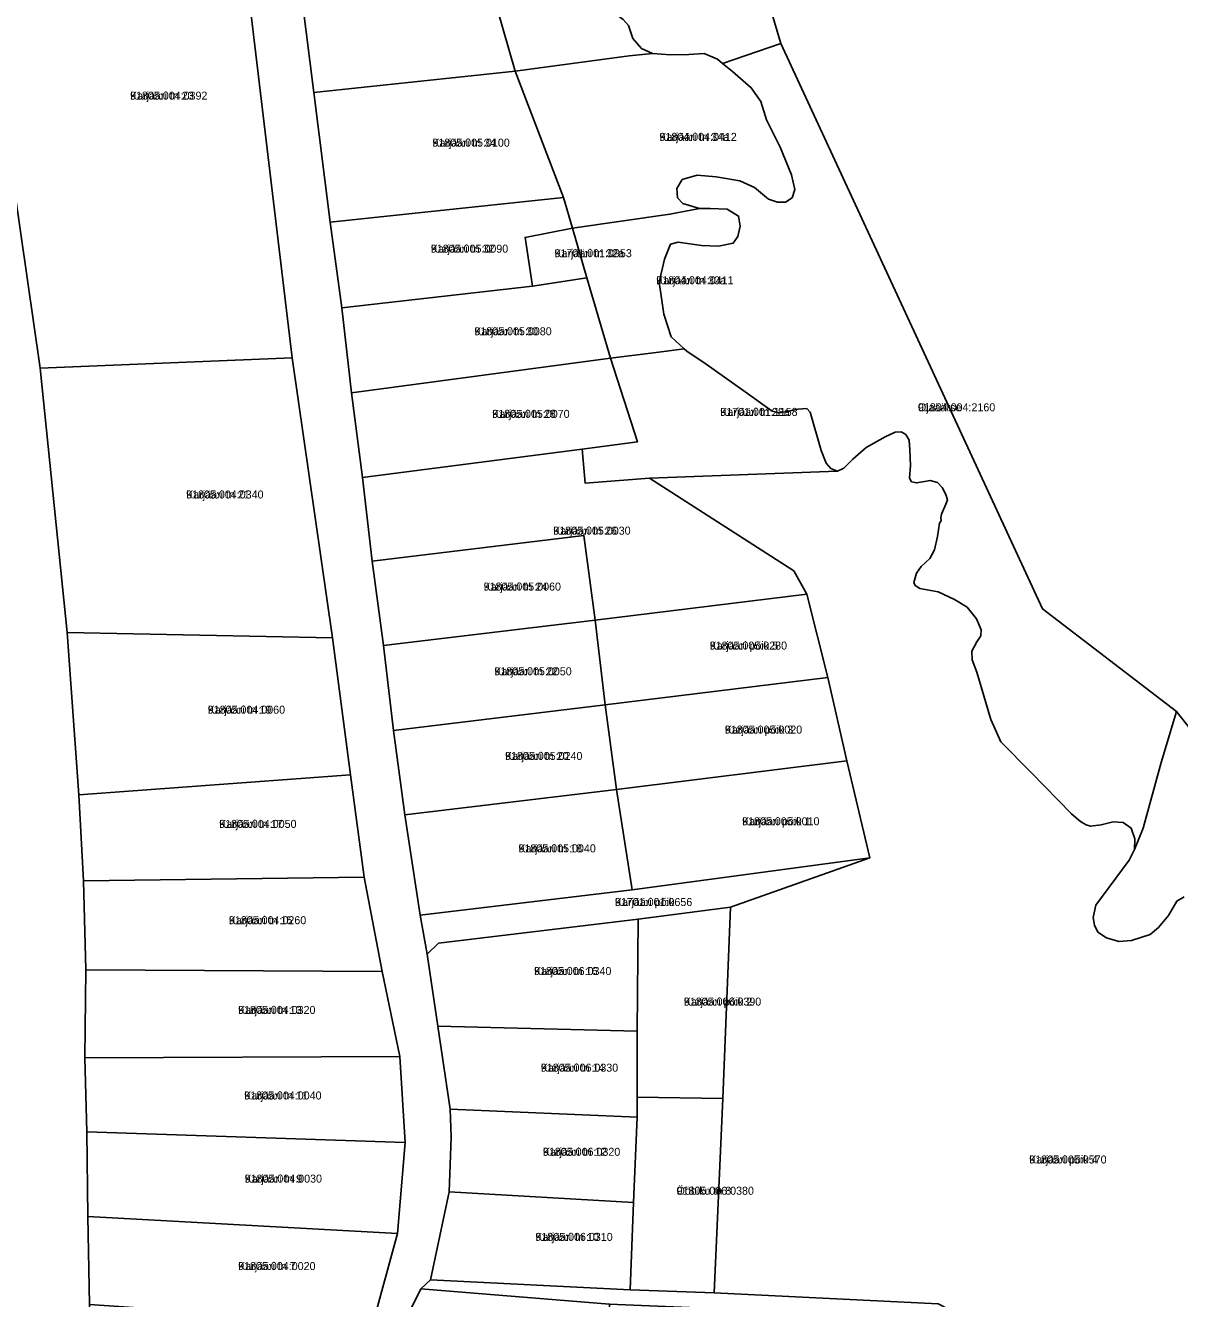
# Model space of a CAD drawing. Extents: x 655954 to 711923, y 6395079 to 6429745.
# Drawn here: x 680691.2 to 680907.6, y 6412288.3 to 6412527 of the extents above; entities that cross this region are included whole.
import ezdxf

# ---------------------------------------------------------------- set-up
doc = ezdxf.new("R2010")
doc.units = 0
for name, color, linetype in [('L_AADRESS', 7, 'Continuous'), ('PIIR', 7, 'Continuous'), ('TUNNUS', 7, 'Continuous')]:
    doc.layers.add(name, color=color, linetype=linetype)

msp = doc.modelspace()

# ---------------------------------------------------------------- linework, layer by layer
at = {"layer": 'PIIR'}
for points in [[(681631.25, 6412784.39), (681524.04, 6412713.27), (681400.11, 6412655.35), (681158.01, 6412526.04), (681124.39, 6412504.87), (681051.56, 6412457.34), (681017.07, 6412435.31), (681004.5, 6412429.19), (680916.58, 6412386.27), (680907.04, 6412398.35), (680881.9, 6412417.62), (680832.81, 6412523.6), (680811.9, 6412594.2), (680849.16, 6412621.46), (680903.12, 6412670.17), (681120.91, 6412675.42), (681109.41, 6412705.01), (680986.04, 6412708.3), (680879.12, 6412719.8), (680806.44, 6412709.75), (680770.1, 6412691.18), (680731.48, 6412687.34), (680659.4, 6412646.08)], [(680811.9, 6412594.2), (680832.81, 6412523.6), (680821.91, 6412519.87), (680820.95, 6412520.65), (680818.44, 6412521.74), (680815.59, 6412521.55), (680812.14, 6412521.48), (680808.77, 6412521.73), (680806.72, 6412522.65), (680805.08, 6412524.57), (680804.29, 6412526.99), (680803.3, 6412528.1)], [(680680.44, 6412556.2), (680693.94, 6412462.74), (680699, 6412413.21), (680701.22, 6412382.72), (680702.09, 6412366.63), (680702.52, 6412349.92), (680702.33, 6412333.42), (680702.73, 6412319.59), (680702.93, 6412303.72), (680703.22, 6412287.2), (680703.43, 6412273.22), (680703.41, 6412251.32), (680702.8, 6412190.26), (680703.14, 6412141.77), (680698.64, 6412123.91), (680691.94, 6412100.04), (680672.88, 6412104.96)], [(680756.31, 6412283.58), (680760.94, 6412300.49), (680762.39, 6412317.56), (680761.38, 6412333.7), (680758.07, 6412349.64), (680754.74, 6412367.34), (680752.17, 6412386.48), (680748.75, 6412412.17), (680741.2, 6412464.7), (680732.66, 6412536.32)], [(680742.3, 6412538.26), (680745.27, 6412514.43), (680748.34, 6412490.12), (680750.51, 6412474.03), (680752.34, 6412458.13), (680754.39, 6412442.26), (680756.2, 6412426.58), (680758.31, 6412410.72), (680760.22, 6412394.83), (680762.32, 6412378.97), (680765.23, 6412360.19), (680766.53, 6412352.85), (680768.52, 6412339.36), (680770.82, 6412323.82), (680771.02, 6412318.58), (680770.65, 6412308.3), (680767.12, 6412291.79), (680765.34, 6412290.1), (680752.9, 6412265.02)], [(680862.31, 6412287.31), (680820.36, 6412289.35), (680821.96, 6412325.79), (680823.43, 6412361.7), (680849.55, 6412370.94), (680845.2, 6412389.13), (680841.62, 6412404.73), (680837.72, 6412420.36), (680835.28, 6412424.73), (680808.22, 6412442.15), (680843.48, 6412443.45), (680844.64, 6412444), (680846.33, 6412445.67), (680848.83, 6412447.85), (680852.42, 6412449.87), (680854.27, 6412450.76), (680855.38, 6412450.81), (680856.28, 6412450.29), (680856.87, 6412449.23), (680857.02, 6412447.46), (680857.18, 6412444.47), (680856.96, 6412442.14), (680857.35, 6412441.46), (680858.25, 6412441.22), (680859.77, 6412441.48), (680860.85, 6412441.69), (680862.19, 6412441.3), (680863.09, 6412440.39), (680863.78, 6412439.05), (680864.07, 6412438.04), (680863.75, 6412437.23), (680862.97, 6412435.39), (680862.85, 6412434.68), (680862.87, 6412434.14), (680862.6, 6412433.71), (680862.23, 6412431.17), (680861.64, 6412428.66), (680860.8, 6412427.05), (680859.18, 6412425.57), (680858.25, 6412424.31), (680857.75, 6412422.53), (680858.02, 6412421.98), (680858.92, 6412421.46), (680862.32, 6412420.79), (680865.43, 6412419.39), (680867.75, 6412417.94), (680869.55, 6412415.72), (680870.4, 6412413.67), (680870.35, 6412412.54), (680869.56, 6412411.45), (680868.66, 6412409.69), (680868.71, 6412408.09), (680869.61, 6412405.76), (680872.21, 6412396.87), (680874.07, 6412392.69), (680879.76, 6412386.94), (680887.36, 6412379.16), (680888.71, 6412378.03), (680889.21, 6412377.62), (680890.06, 6412377.14), (680890.93, 6412376.9), (680892.91, 6412377.1), (680895.18, 6412377.69), (680897.04, 6412377.58), (680898.52, 6412376.49), (680899.19, 6412374.52), (680899.13, 6412372.51), (680898.17, 6412370.5), (680891.93, 6412362.05), (680891.41, 6412359.77), (680891.62, 6412358.34), (680892.25, 6412357.02), (680893.89, 6412355.91), (680896.22, 6412355.28), (680898.6, 6412355.43), (680902.09, 6412356.54), (680903.63, 6412357.87), (680905.53, 6412360.14), (680907.07, 6412362.84), (680908.44, 6412363.63)], [(680908.44, 6412363.63), (680907.07, 6412362.84), (680905.53, 6412360.14), (680903.63, 6412357.87), (680902.09, 6412356.54), (680898.6, 6412355.43), (680896.22, 6412355.28), (680893.89, 6412355.91), (680892.25, 6412357.02), (680891.62, 6412358.34), (680891.41, 6412359.77), (680891.93, 6412362.05), (680898.17, 6412370.5), (680899.13, 6412372.51), (680900.78, 6412376.52), (680904.16, 6412388.82), (680907.04, 6412398.35), (680916.58, 6412386.27)]]:
    msp.add_lwpolyline(points, dxfattribs=at)
for points in [[(680710.88, 6412562.75), (680718, 6412533.21), (680732.66, 6412536.32), (680741.2, 6412464.7), (680693.94, 6412462.74), (680680.44, 6412556.2)], [(680776.14, 6412542.38), (680801.78, 6412545.87), (680805.78, 6412546.39), (680807.55, 6412543.41), (680805.54, 6412539.25), (680801.77, 6412537.65), (680797.26, 6412535.89), (680795.9, 6412535.1), (680795.63, 6412533.76), (680796.33, 6412532.41), (680797.99, 6412531.65), (680799.57, 6412531.08), (680801.29, 6412529.6), (680803.3, 6412528.1), (680804.29, 6412526.99), (680805.08, 6412524.57), (680806.72, 6412522.65), (680808.77, 6412521.73), (680804.4, 6412521.32), (680783.04, 6412518.42)], [(680745.27, 6412514.43), (680742.3, 6412538.26), (680776.14, 6412542.38), (680783.04, 6412518.42)], [(680832.2, 6412493.89), (680830.5, 6412494.41), (680827.92, 6412496.63), (680825.15, 6412497.88), (680820.72, 6412498.59), (680817.12, 6412498.9), (680814.36, 6412498.09), (680813.34, 6412496.44), (680813.49, 6412494.7), (680814.48, 6412493.63), (680817.6, 6412492.68), (680812.05, 6412491.59), (680793.76, 6412488.98), (680792.1, 6412494.76), (680783.04, 6412518.42), (680804.4, 6412521.32), (680808.77, 6412521.73), (680812.14, 6412521.48), (680815.59, 6412521.55), (680818.44, 6412521.74), (680820.95, 6412520.65), (680821.91, 6412519.87), (680823.76, 6412518.34), (680827.28, 6412515.31), (680829.09, 6412512.76), (680830.14, 6412509.33), (680832.69, 6412504.2), (680834.85, 6412498.99), (680835.48, 6412496.27), (680834.97, 6412494.7), (680833.71, 6412493.84)], [(680825.69, 6412458.62), (680818.81, 6412463.48), (680815.2, 6412465.95), (680814.71, 6412466.39), (680812.27, 6412468.61), (680810.89, 6412472.89), (680810.04, 6412478.85), (680811.04, 6412483.2), (680812.16, 6412485.99), (680813.6, 6412486.39), (680817.96, 6412485.73), (680821.15, 6412485.62), (680823.92, 6412486.2), (680824.79, 6412487.43), (680825.21, 6412489.34), (680824.93, 6412491.26), (680822.75, 6412492.55), (680819.58, 6412492.67), (680817.6, 6412492.68), (680814.48, 6412493.63), (680813.49, 6412494.7), (680813.34, 6412496.44), (680814.36, 6412498.09), (680817.12, 6412498.9), (680820.72, 6412498.59), (680825.15, 6412497.88), (680827.92, 6412496.63), (680830.5, 6412494.41), (680832.2, 6412493.89), (680833.71, 6412493.84), (680834.97, 6412494.7), (680835.48, 6412496.27), (680834.85, 6412498.99), (680832.69, 6412504.2), (680830.14, 6412509.33), (680829.09, 6412512.76), (680827.28, 6412515.31), (680823.76, 6412518.34), (680821.91, 6412519.87), (680832.81, 6412523.6), (680881.9, 6412417.62), (680907.04, 6412398.35), (680904.16, 6412388.82), (680900.78, 6412376.52), (680899.13, 6412372.51), (680899.19, 6412374.52), (680898.52, 6412376.49), (680897.04, 6412377.58), (680895.18, 6412377.69), (680892.91, 6412377.1), (680890.93, 6412376.9), (680890.06, 6412377.14), (680889.21, 6412377.62), (680888.71, 6412378.03), (680887.36, 6412379.16), (680879.76, 6412386.94), (680874.07, 6412392.69), (680872.21, 6412396.87), (680869.61, 6412405.76), (680868.71, 6412408.09), (680868.66, 6412409.69), (680869.56, 6412411.45), (680870.35, 6412412.54), (680870.4, 6412413.67), (680869.55, 6412415.72), (680867.75, 6412417.94), (680865.43, 6412419.39), (680862.32, 6412420.79), (680858.92, 6412421.46), (680858.02, 6412421.98), (680857.75, 6412422.53), (680858.25, 6412424.31), (680859.18, 6412425.57), (680860.8, 6412427.05), (680861.64, 6412428.66), (680862.23, 6412431.17), (680862.6, 6412433.71), (680862.87, 6412434.14), (680862.85, 6412434.68), (680862.97, 6412435.39), (680863.75, 6412437.23), (680864.07, 6412438.04), (680863.78, 6412439.05), (680863.09, 6412440.39), (680862.19, 6412441.3), (680860.85, 6412441.69), (680859.77, 6412441.48), (680858.25, 6412441.22), (680857.35, 6412441.46), (680856.96, 6412442.14), (680857.18, 6412444.47), (680857.02, 6412447.46), (680856.87, 6412449.23), (680856.28, 6412450.29), (680855.38, 6412450.81), (680854.27, 6412450.76), (680852.42, 6412449.87), (680848.83, 6412447.85), (680846.33, 6412445.67), (680844.64, 6412444), (680843.48, 6412443.45), (680842.21, 6412443.92), (680841.32, 6412444.91), (680840.41, 6412447.31), (680838.36, 6412454.5), (680837.71, 6412455.17), (680836.08, 6412455.08), (680832.65, 6412454.38), (680831.21, 6412454.66)], [(680745.27, 6412514.43), (680783.04, 6412518.42), (680792.1, 6412494.76), (680748.34, 6412490.12)], [(680748.34, 6412490.12), (680792.1, 6412494.76), (680793.76, 6412488.98), (680784.89, 6412487.26), (680786.28, 6412478.13), (680750.51, 6412474.03)], [(680810.89, 6412472.89), (680812.27, 6412468.61), (680814.71, 6412466.39), (680809.47, 6412465.71), (680800.91, 6412464.6), (680796.45, 6412479.7), (680793.76, 6412488.98), (680812.05, 6412491.59), (680817.6, 6412492.68), (680819.58, 6412492.67), (680822.75, 6412492.55), (680824.93, 6412491.26), (680825.21, 6412489.34), (680824.79, 6412487.43), (680823.92, 6412486.2), (680821.15, 6412485.62), (680817.96, 6412485.73), (680813.6, 6412486.39), (680812.16, 6412485.99), (680811.04, 6412483.2), (680810.04, 6412478.85)], [(680796.45, 6412479.7), (680786.28, 6412478.13), (680784.89, 6412487.26), (680793.76, 6412488.98)], [(680752.34, 6412458.13), (680750.51, 6412474.03), (680786.28, 6412478.13), (680796.45, 6412479.7), (680800.91, 6412464.6)], [(680693.94, 6412462.74), (680741.2, 6412464.7), (680748.75, 6412412.17), (680699, 6412413.21)], [(680800.91, 6412464.6), (680805.96, 6412448.92), (680795.6, 6412447.58), (680754.39, 6412442.26), (680752.34, 6412458.13)], [(680831.21, 6412454.66), (680832.65, 6412454.38), (680836.08, 6412455.08), (680837.71, 6412455.17), (680838.36, 6412454.5), (680840.41, 6412447.31), (680841.32, 6412444.91), (680842.21, 6412443.92), (680843.48, 6412443.45), (680808.22, 6412442.15), (680796.15, 6412441.18), (680795.6, 6412447.58), (680805.96, 6412448.92), (680800.91, 6412464.6), (680809.47, 6412465.71), (680814.71, 6412466.39), (680815.2, 6412465.95), (680818.81, 6412463.48), (680825.69, 6412458.62)], [(680756.2, 6412426.58), (680754.39, 6412442.26), (680795.6, 6412447.58), (680796.15, 6412441.18), (680808.22, 6412442.15), (680835.28, 6412424.73), (680837.72, 6412420.36), (680798.02, 6412415.49), (680795.91, 6412431.35)], [(680756.2, 6412426.58), (680795.91, 6412431.35), (680798.02, 6412415.49), (680758.31, 6412410.72)], [(680799.93, 6412399.6), (680798.02, 6412415.49), (680837.72, 6412420.36), (680841.62, 6412404.73)], [(680758.31, 6412410.72), (680798.02, 6412415.49), (680799.93, 6412399.6), (680760.22, 6412394.83)], [(680748.75, 6412412.17), (680752.17, 6412386.48), (680701.22, 6412382.72), (680699, 6412413.21)], [(680802.04, 6412383.72), (680799.93, 6412399.6), (680841.62, 6412404.73), (680845.2, 6412389.13)], [(680760.22, 6412394.83), (680799.93, 6412399.6), (680802.04, 6412383.72), (680762.32, 6412378.97)], [(680849.55, 6412370.94), (680804.95, 6412364.94), (680802.04, 6412383.72), (680845.2, 6412389.13)], [(680752.17, 6412386.48), (680754.74, 6412367.34), (680702.09, 6412366.63), (680701.22, 6412382.72)], [(680762.32, 6412378.97), (680802.04, 6412383.72), (680804.95, 6412364.94), (680765.23, 6412360.19)], [(680766.53, 6412352.85), (680765.23, 6412360.19), (680804.95, 6412364.94), (680849.55, 6412370.94), (680823.43, 6412361.7), (680806.1, 6412359.44), (680768.67, 6412354.94)], [(680754.74, 6412367.34), (680758.07, 6412349.64), (680702.52, 6412349.92), (680702.09, 6412366.63)], [(680806.1, 6412359.44), (680823.43, 6412361.7), (680821.96, 6412325.79), (680805.89, 6412326.04), (680805.92, 6412338.47)], [(680768.52, 6412339.36), (680766.53, 6412352.85), (680768.67, 6412354.94), (680806.1, 6412359.44), (680805.92, 6412338.47)], [(680758.07, 6412349.64), (680761.38, 6412333.7), (680702.33, 6412333.42), (680702.52, 6412349.92)], [(680770.82, 6412323.82), (680768.52, 6412339.36), (680805.92, 6412338.47), (680805.89, 6412326.04), (680805.88, 6412322.32)], [(680761.38, 6412333.7), (680762.39, 6412317.56), (680702.73, 6412319.59), (680702.33, 6412333.42)], [(680805.89, 6412326.04), (680821.96, 6412325.79), (680820.36, 6412289.35), (680804.61, 6412289.94), (680805.19, 6412306.32), (680805.88, 6412322.32)], [(680771.02, 6412318.58), (680770.82, 6412323.82), (680805.88, 6412322.32), (680805.19, 6412306.32), (680770.65, 6412308.3)], [(680762.39, 6412317.56), (680760.94, 6412300.49), (680702.93, 6412303.72), (680702.73, 6412319.59)], [(680770.65, 6412308.3), (680805.19, 6412306.32), (680804.61, 6412289.94), (680767.12, 6412291.79)], [(680760.94, 6412300.49), (680756.31, 6412283.58), (680703.22, 6412287.2), (680702.93, 6412303.72)], [(680752.9, 6412265.02), (680765.34, 6412290.1), (680800.73, 6412287.27), (680799.29, 6412261.81)], [(680870.69, 6412279.41), (680880.28, 6412236.06), (680881.55, 6412222.94), (680877.37, 6412222.76), (680877.54, 6412230), (680877.04, 6412234.3), (680871.65, 6412258.51), (680868.45, 6412275.6), (680864.46, 6412281.65), (680860.25, 6412284.01), (680852.84, 6412285.3), (680835.2, 6412285.8), (680800.73, 6412287.27), (680765.34, 6412290.1), (680767.12, 6412291.79), (680804.61, 6412289.94), (680820.36, 6412289.35), (680862.31, 6412287.31), (680867.78, 6412284.5)]]:
    msp.add_lwpolyline(points, close=True, dxfattribs=at)

# ---------------------------------------------------------------- texts
at = {"layer": 'L_AADRESS'}
for s, p in [('Karjääri tn 23', (680710.82, 6412513.09)), ('Karjääri tn 34', (680767.51, 6412504.27)), ('Karjääri tn 34a', (680810.08, 6412505.36)), ('Karjääri tn 32', (680767.22, 6412484.4)), ('Karjääri tn 32a', (680790.39, 6412483.55)), ('Karjääri tn 30a', (680809.48, 6412478.47)), ('Karjääri tn 30', (680775.37, 6412468.91)), ('Karjääri tn 28', (680778.73, 6412453.43)), ('Karjääri tn 28a', (680821.48, 6412453.79)), ('Ojaäärse', (680858.54, 6412454.66)), ('Karjääri tn 21', (680721.34, 6412438.31)), ('Karjääri tn 26', (680790.17, 6412431.53)), ('Karjääri tn 24', (680777.11, 6412421.04)), ('Karjääri põik 5', (680819.5, 6412409.98)), ('Karjääri tn 22', (680779.12, 6412405.16)), ('Karjääri tn 19', (680725.38, 6412397.96)), ('Karjääri põik 3', (680822.34, 6412394.23)), ('Karjääri tn 20', (680781.13, 6412389.29)), ('Karjääri põik 1', (680825.58, 6412377.04)), ('Karjääri tn 17', (680727.53, 6412376.55)), ('Karjääri tn 18', (680783.64, 6412371.96)), ('Karjääri põik', (680801.73, 6412361.9)), ('Karjääri tn 15', (680729.35, 6412358.49)), ('Karjääri tn 16', (680786.56, 6412348.96)), ('Karjääri tn 13', (680731.08, 6412341.67)), ('Karjääri põik 2', (680814.66, 6412343.23)), ('Karjääri tn 14', (680787.84, 6412330.84)), ('Karjääri tn 11', (680732.22, 6412325.63)), ('Karjääri tn 12', (680788.23, 6412315.07)), ('Karjääri põik 4', (680879.41, 6412313.63)), ('Karjääri tn 9', (680732.3, 6412310.04)), ('Ööbiku tn 8', (680813.29, 6412307.77)), ('Karjääri tn 10', (680786.81, 6412299.12)), ('Karjääri tn 7', (680731.09, 6412293.65))]:
    msp.add_text(s, height=1.5, dxfattribs=at).set_placement(p)
at = {"layer": 'TUNNUS'}
for s, p in [('91805:004:0392', (680710.82, 6412513.09)), ('91805:005:0100', (680767.51, 6412504.27)), ('91804:004:0412', (680810.08, 6412505.36)), ('91805:005:0090', (680767.22, 6412484.4)), ('91701:001:0953', (680790.39, 6412483.55)), ('91804:004:0411', (680809.48, 6412478.47)), ('91805:005:0080', (680775.37, 6412468.91)), ('91805:005:0070', (680778.73, 6412453.43)), ('91701:001:1158', (680821.48, 6412453.79)), ('91804:004:2160', (680858.54, 6412454.66)), ('91805:004:0340', (680721.34, 6412438.31)), ('91805:005:0030', (680790.17, 6412431.53)), ('91805:005:0060', (680777.11, 6412421.04)), ('91805:005:0280', (680819.5, 6412409.98)), ('91805:005:0050', (680779.12, 6412405.16)), ('91805:004:0060', (680725.38, 6412397.96)), ('91805:005:0020', (680822.34, 6412394.23)), ('91805:005:0240', (680781.13, 6412389.29)), ('91805:005:0010', (680825.58, 6412377.04)), ('91805:004:0050', (680727.53, 6412376.55)), ('91805:005:0040', (680783.64, 6412371.96)), ('91701:001:0656', (680801.73, 6412361.9)), ('91805:004:0260', (680729.35, 6412358.49)), ('91805:006:0340', (680786.56, 6412348.96)), ('91805:004:0320', (680731.08, 6412341.67)), ('91805:006:0390', (680814.66, 6412343.23)), ('91805:006:0330', (680787.84, 6412330.84)), ('91805:004:0040', (680732.22, 6412325.63)), ('91805:006:0320', (680788.23, 6412315.07)), ('91805:005:0570', (680879.41, 6412313.63)), ('91805:004:0030', (680732.3, 6412310.04)), ('91805:006:0380', (680813.29, 6412307.77)), ('91805:006:0310', (680786.81, 6412299.12)), ('91805:004:0020', (680731.09, 6412293.65))]:
    msp.add_text(s, height=1.5, dxfattribs=at).set_placement(p)

doc.saveas('drawing.dxf')
